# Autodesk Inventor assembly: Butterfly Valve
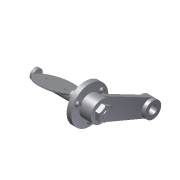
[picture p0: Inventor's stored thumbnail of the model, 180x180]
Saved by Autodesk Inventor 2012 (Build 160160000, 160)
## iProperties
Created: 2011-07
Part Number: Butterfly Valve
Document SubType Name: Assembly
Designer: CadCim
Author: CadCim
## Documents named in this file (8)
- C:\Users\CadCim\Documents\SAILESH\inventor-2011-fact-prt\c09_inv_2011-prt\c09_inv_2012_prt\Tutorials\c09_tut01_inv\Butterfly Valve.iam
- C:\Users\CadCim\Documents\SAILESH\inventor-2011-fact-prt\c09_inv_2011-prt\c09_inv_2012_prt\Tutorials\c09_tut01_inv\Body.ipt
- C:\Users\CadCim\Documents\SAILESH\inventor-2011-fact-prt\c09_inv_2011-prt\c09_inv_2012_prt\Tutorials\c09_tut01_inv\Shaft.ipt
- C:\Users\CadCim\Documents\SAILESH\inventor-2011-fact-prt\c09_inv_2011-prt\c09_inv_2012_prt\Tutorials\c09_tut01_inv\Retainer.ipt
- C:\Users\CadCim\Documents\SAILESH\inventor-2011-fact-prt\c09_inv_2011-prt\c09_inv_2012_prt\Tutorials\c09_tut01_inv\Arm.ipt
- C:\Users\CadCim\Documents\SAILESH\inventor-2011-fact-prt\c09_inv_2011-prt\c09_inv_2012_prt\Tutorials\c09_tut01_inv\Plate.ipt
- C:\Users\CadCim\Documents\SAILESH\inventor-2011-fact-prt\c09_inv_2011-prt\c09_inv_2012_prt\Tutorials\c09_tut01_inv\Screw.ipt
- C:\Users\CadCim\Documents\SAILESH\inventor-2011-fact-prt\c09_inv_2011-prt\c09_inv_2012_prt\Tutorials\c09_tut01_inv\Nut.ipt
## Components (9 placed, 7 different names)
1. Body:1 — Insert:1, Insert:2, Insert:3, Angle:1
2. Shaft:1 — Insert:1, Mate:1, Angle:1, Insert:5, Insert:6, Insert:10
3. Retainer:1 — Insert:2, Insert:3, Insert:4, Insert:7, Insert:8, Insert:9
4. Arm:1 — Insert:4, Mate:1
5. Plate:1 — Insert:5, Insert:6
6. Screw:1 — Insert:7
7. Screw:2 — Insert:8
8. Screw:3 — Insert:9
9. Nut:1 — Insert:10
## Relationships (12: Insert 10, Mate 1, Angle 1)
- Insert:1: Body:1 ↔ Shaft:1
- Insert:2: Body:1 ↔ Retainer:1
- Insert:3: Body:1 ↔ Retainer:1
- Insert:4: Retainer:1 ↔ Arm:1
- Mate:1: Shaft:1 ↔ Arm:1
- Angle:1: Body:1 ↔ Shaft:1
- Insert:5: Shaft:1 ↔ Plate:1
- Insert:6: Shaft:1 ↔ Plate:1
- Insert:7: Retainer:1 ↔ Screw:1
- Insert:8: Retainer:1 ↔ Screw:2
- Insert:9: Retainer:1 ↔ Screw:3
- Insert:10: Shaft:1 ↔ Nut:1
